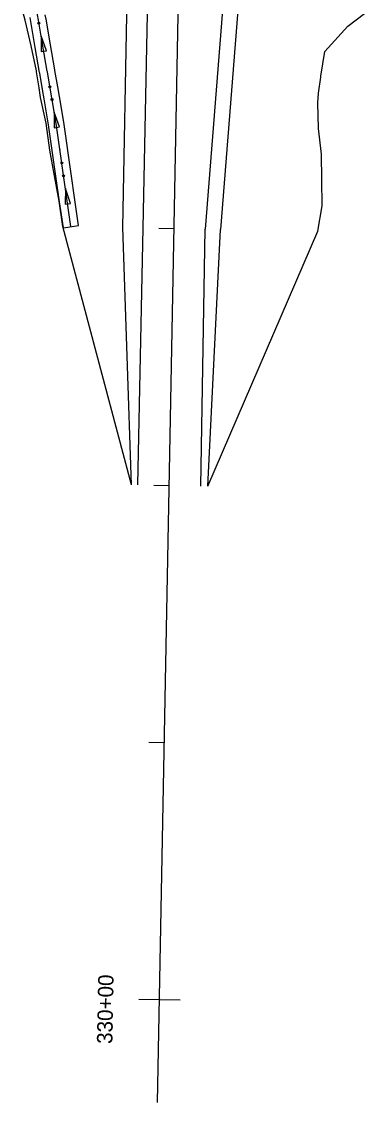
# Model space of a CAD drawing. Extents: x 948761 to 996004, y 1858548 to 1925175.
# Drawn here: x 960908.4 to 961041.7, y 1904030.2 to 1904450.6 of the extents above; entities that cross this region are included whole.
import ezdxf

# ---------------------------------------------------------------- set-up
doc = ezdxf.new("R2010")
doc.units = 0
for name, color, linetype in [('62', 7, 'Continuous'), ('R_Horz Alg', 7, 'Continuous'), ('R_Horz Alg Annot', 7, 'Continuous'), ('R_Proposed Const Limits', 7, 'Continuous'), ('R_Proposed Road', 7, 'Continuous')]:
    doc.layers.add(name, color=color, linetype=linetype)

msp = doc.modelspace()

# ---------------------------------------------------------------- linework, layer by layer
at = {"layer": '62'}
for p, q in [((960915.99, 1904445.04), (960915.97, 1904438.95)), ((960918.05, 1904439.31), (960915.99, 1904445.04)), ((960915.97, 1904438.95), (960918.05, 1904439.31)), ((960921.1, 1904415.44), (960921.07, 1904409.35)), ((960923.15, 1904409.7), (960921.1, 1904415.44)), ((960921.07, 1904409.35), (960923.15, 1904409.7)), ((960925.48, 1904385.72), (960925.28, 1904379.63)), ((960927.38, 1904379.93), (960925.48, 1904385.72)), ((960925.28, 1904379.63), (960927.38, 1904379.93)), ((960924.64, 1904370.45), (960930.58, 1904371.3))]:
    msp.add_line(p, q, dxfattribs=at)
for points in [[(960927.61, 1904370.88), (960926.17, 1904380.9), (960924.73, 1904390.93), (960923.3, 1904400.96), (960921.86, 1904410.99), (960920.14, 1904421.03), (960919.49, 1904424.76), (960918.41, 1904431.06), (960918.35, 1904431.37), (960916.67, 1904441.1), (960914.94, 1904451.13), (960914.21, 1904455.35), (960914.07, 1904456.15)], [(960924.64, 1904370.45), (960923.2, 1904380.48), (960921.76, 1904390.51), (960918.89, 1904410.53), (960917.18, 1904420.52), (960916.54, 1904424.25), (960915.45, 1904430.55), (960915.4, 1904430.86), (960913.72, 1904440.59), (960911.98, 1904450.62), (960911.71, 1904452.2)], [(960930.58, 1904371.3), (960929.14, 1904381.33), (960927.7, 1904391.36), (960924.82, 1904411.46), (960923.1, 1904421.53), (960922.45, 1904425.27), (960921.36, 1904431.57), (960921.31, 1904431.88), (960919.63, 1904441.61), (960917.9, 1904451.64), (960917.62, 1904453.22)], [(960918.54, 1904430.26), (960918.41, 1904431.06), (960918.35, 1904431.37), (960916.67, 1904441.1), (960915.99, 1904445.04)], [(960918.55, 1904430.22), (960918.54, 1904430.26)], [(960923.35, 1904400.61), (960923.3, 1904400.96), (960921.86, 1904410.99), (960921.1, 1904415.44)], [(960923.35, 1904400.57), (960923.35, 1904400.61)], [(960927.61, 1904370.88), (960926.17, 1904380.9), (960925.48, 1904385.72)]]:
    msp.add_lwpolyline(points, dxfattribs=at)
for centre in [(960915.1, 1904449.97), (960919.36, 1904425.3), (960920.22, 1904420.37), (960924.02, 1904395.63), (960924.73, 1904390.67)]:
    msp.add_circle(centre, 0.375, dxfattribs=at)
at = {"layer": 'R_Horz Alg'}
msp.add_line((960961.25, 1904030.17), (960973.94, 1904695.88), dxfattribs=at)
at = {"layer": 'R_Horz Alg Annot'}
for points in [[(960961.73, 1904370.22), (960967.73, 1904370.11)], [(960959.83, 1904270.24), (960965.83, 1904270.13)], [(960957.92, 1904170.26), (960963.92, 1904170.15)], [(960954.02, 1904070.32), (960970.01, 1904070.01)]]:
    msp.add_lwpolyline(points, dxfattribs=at)
at = {"layer": 'R_Proposed Const Limits'}
for points in [[(960951.17, 1904270.41), (960924.43, 1904370.9), (960922.96, 1904380.71), (960921.26, 1904390.63), (960919.32, 1904400.67), (960917.92, 1904411.07), (960915.74, 1904421.11), (960915.23, 1904424.84), (960914.23, 1904431.14), (960914.17, 1904431.45), (960912.11, 1904441.18), (960909.83, 1904451.23), (960908.64, 1904455.46), (960908.41, 1904456.26), (960910.54, 1904461.22), (960913.34, 1904481.24)], [(961035.23, 1904448.84), (961041.69, 1904453.72)], [(960980.76, 1904269.84), (961023.6, 1904369.04), (961025.26, 1904379.02), (961025.13, 1904389.02), (961025.03, 1904399.02), (961023.79, 1904409.05), (961023.56, 1904419.05), (961023.83, 1904422.77), (961024.78, 1904429.03), (961024.82, 1904429.34), (961026.27, 1904439.01), (961035.23, 1904448.84)]]:
    msp.add_lwpolyline(points, dxfattribs=at)
at = {"layer": 'R_Proposed Road'}
for p, q in [((960947.74, 1904370.5), (960953.94, 1904696.26)), ((960955.73, 1904370.34), (960961.94, 1904696.11)), ((960995.54, 1904569.62), (960979.73, 1904369.88)), ((961001.53, 1904569.32), (960985.74, 1904369.77)), ((960951.17, 1904270.41), (960947.74, 1904370.5)), ((960953.54, 1904270.36), (960955.73, 1904370.34)), ((960978.11, 1904269.89), (960979.73, 1904369.88))]:
    msp.add_line(p, q, dxfattribs=at)
msp.add_lwpolyline([(960980.76, 1904269.84), (960985.74, 1904369.77)], dxfattribs=at)

# ---------------------------------------------------------------- texts
at = {"layer": 'R_Horz Alg'}
msp.add_text('+', height=1, rotation=88.9082, dxfattribs=at).set_placement((960962.52, 1904070.16))
at = {"layer": 'R_Horz Alg Annot'}
msp.add_text('330+00', height=6, rotation=88.9082, dxfattribs=at).set_placement((960943.68, 1904052.87))

doc.saveas('drawing.dxf')
